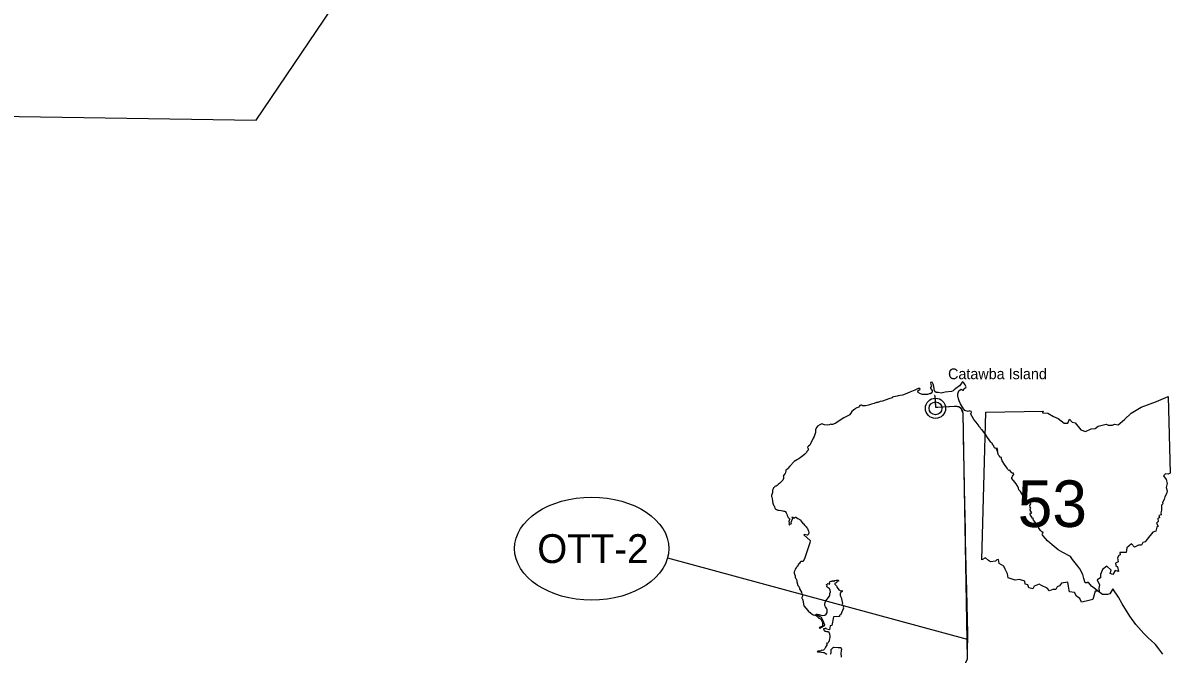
# Model space of a CAD drawing. Extents: x -82 to 873, y 0 to 440.
# Drawn here: x 400.6 to 512.1, y 215.6 to 276.9 of the extents above; entities that cross this region are included whole.
import ezdxf

# ---------------------------------------------------------------- set-up
doc = ezdxf.new("R2010")
doc.units = 0
for name, color, linetype in [('DV_X_Corp_Line', 7, 'Continuous'), ('DV_X_County_Line', 7, 'Continuous'), ('GM_P_US_Alignment', 7, 'Continuous'), ('GM_X_County', 7, 'Continuous'), ('GM_X_Interstate_Route', 7, 'Continuous'), ('PV_P_Text', 7, 'Continuous'), ('SH_Data', 7, 'Continuous')]:
    doc.layers.add(name, color=color, linetype=linetype)

msp = doc.modelspace()

# ---------------------------------------------------------------- linework, layer by layer
at = {"layer": 'DV_X_Corp_Line'}
for radius in [0.982, 0.623]:
    msp.add_circle((489.31, 239.51), radius, dxfattribs=at)
at = {"layer": 'DV_X_County_Line'}
for p, q in [((423.26, 267.51), (499.56, 380.26)), ((350.92, 268.65), (423.26, 267.51))]:
    msp.add_line(p, q, dxfattribs=at)
at = {"layer": 'GM_P_US_Alignment'}
msp.add_lwpolyline([(473.37, 168.87), (473.54, 173.99), (473.96, 183.62), (473.91, 187.53), (484.23, 206.18), (490.74, 211.48), (492.43, 215.18), (491.99, 239.02), (491.81, 239.48), (491.57, 239.64), (491.32, 239.67), (489.33, 239.58), (489.28, 240.63)], dxfattribs=at)
at = {"layer": 'GM_X_County'}
for points in [[(511.42, 215.64), (511.03, 216.15), (510.69, 216.58), (510.27, 216.95), (509.98, 217.21), (509.57, 217.62), (508.8, 218.51), (508.21, 219.33), (507.47, 220.53), (507.11, 221.17), (506.56, 221.96), (506.26, 221.5), (506.03, 221.42), (505.55, 221.43), (505.42, 221.51), (504.48, 222.22), (504.22, 222.56), (504.15, 222.62), (504.06, 222.57), (503.86, 222.56), (503.73, 222.99), (503.62, 223.37), (503.33, 223.91), (503.14, 224.16), (502.62, 224.82), (502.44, 225.13), (501.68, 225.5), (501.23, 225.76), (500.65, 226.25), (500.21, 226.63), (499.76, 227.11), (499.7, 227.21), (499.68, 227.29), (499.71, 227.35), (499.75, 227.37), (499.77, 227.48), (499.72, 227.48), (499.65, 227.52), (499.53, 227.63), (499.11, 228.3), (498.99, 228.45), (498.84, 228.64), (498.81, 228.73), (498.82, 228.8), (498.75, 228.84), (498.55, 229.12), (498.52, 229.22), (498.52, 229.29), (498.54, 229.35), (498.59, 229.37), (498.62, 229.33), (498.66, 229.35), (498.62, 229.44), (498.52, 229.61), (498.52, 229.75), (498.56, 229.75), (498.58, 229.82), (498.5, 229.92), (498.47, 230.1), (498.54, 230.17), (498.58, 230.27), (498.49, 230.39), (498.2, 230.6), (497.99, 230.8), (497.78, 231.1), (497.56, 231.44), (497.41, 231.6), (497.39, 231.75), (497.31, 231.92), (497.15, 232.17), (497.02, 232.32), (496.74, 232.7), (496.72, 232.81), (496.76, 232.84), (496.84, 232.87), (496.8, 232.95), (496.84, 233.03), (496.91, 233.06), (496.9, 233.21), (496.85, 233.22), (496.75, 233.2), (496.65, 233.3), (496.54, 233.49), (496.47, 233.46), (496.41, 233.49), (496.33, 233.56), (496.28, 233.7), (496.2, 233.8), (496.07, 233.96), (495.79, 234.42), (495.72, 234.59), (495.71, 234.73), (495.61, 234.77), (495.52, 234.85), (495.46, 234.94), (495.39, 235.05), (495.37, 235.15), (495.36, 235.31), (495.32, 235.32), (495.3, 235.36), (495.31, 235.43), (495.37, 235.44), (495.37, 235.48), (495.28, 235.48), (495.22, 235.53), (495.29, 235.55), (495.32, 235.61), (495.16, 235.6), (495.15, 235.67), (495.1, 235.64), (495.03, 235.68), (494.97, 235.81), (494.98, 235.86), (494.89, 235.92), (494.85, 236.01), (494.84, 236.1), (494.79, 236.12), (494.68, 236.23), (494.35, 236.68), (494.21, 236.94), (493.86, 237.41), (493.78, 237.45), (493.72, 237.52), (493.66, 237.66), (493.58, 237.68), (493.45, 237.91), (493.27, 238.16), (493.05, 238.43), (492.7, 239.01), (492.77, 239.02), (492.81, 239.13), (492.76, 239.21), (492.62, 239.26), (492.57, 239.22), (492.54, 239.23), (492.49, 239.21), (492.15, 239.31), (492.02, 239.47), (491.75, 239.93), (491.6, 240.25), (491.54, 240.43), (491.48, 240.73), (491.49, 240.93), (491.59, 241.2), (491.7, 241.31), (491.8, 241.38), (491.88, 241.35), (491.98, 241.28), (492.03, 241.27), (492.11, 241.42), (492.25, 241.54), (492.3, 241.6), (492.18, 241.8), (492.07, 241.99), (491.97, 242.08), (491.89, 242.04), (491.78, 241.86), (491.64, 241.71), (491.29, 241.45), (491.13, 241.31), (491.01, 241.22), (490.87, 241.15), (490.26, 241.07), (489.86, 240.99), (489.56, 241.04), (489.37, 241.06), (489.23, 241.13), (489.2, 241.21), (489.16, 241.63), (489.07, 241.86), (489, 242.04), (488.81, 242.01), (488.85, 241.81), (488.92, 241.58), (488.8, 241.54), (488.86, 241.41), (488.99, 241.23), (488.99, 241.09), (488.94, 241.01), (488.81, 240.93), (488.8, 240.95), (488.53, 240.86), (488.25, 240.84), (488.06, 240.86), (487.86, 240.92), (487.63, 241.06), (487.58, 241.21), (487.81, 241.38), (487.78, 241.44), (487.62, 241.43), (487.31, 241.26), (487.13, 241.22), (486.82, 241.08), (486.36, 240.88), (486.09, 240.78), (485.87, 240.77), (485.69, 240.72), (485.57, 240.69), (485.41, 240.65), (485.23, 240.63), (485.12, 240.58), (485.08, 240.54), (484.76, 240.43), (484.17, 240.21), (483.94, 240.17), (483.7, 240.06), (483.58, 240.09), (483.36, 239.99), (483.09, 239.9), (482.79, 239.81), (482.49, 239.75), (482.31, 239.75), (482.21, 239.76), (482.15, 239.8), (482.04, 239.82), (481.99, 239.79), (481.96, 239.78), (481.92, 239.75), (481.91, 239.7), (481.9, 239.67), (481.84, 239.63), (481.66, 239.55), (481.52, 239.49), (481.46, 239.44), (481.33, 239.34), (481.18, 239.19), (481.07, 239.04), (480.94, 238.88), (480.93, 238.86), (480.58, 238.68), (480.38, 238.58), (479.56, 238.04), (479.29, 237.94), (479.21, 237.94), (479.14, 237.96), (478.98, 237.9), (478.76, 237.86), (478.5, 237.9), (478.25, 237.99), (478.06, 237.91), (477.84, 237.76), (477.76, 237.69), (477.64, 237.44), (477.63, 237.17), (477.5, 236.77), (477.42, 236.61), (477.15, 236.05), (477.09, 235.93), (476.97, 235.82), (476.86, 235.74), (476.88, 235.62), (476.93, 235.6), (476.92, 235.46), (476.81, 235.33), (476.76, 235.22), (476.59, 235.04), (476.25, 234.75), (476.19, 234.73), (476.03, 234.6), (475.88, 234.55), (475.57, 234.33), (475.14, 233.89), (474.91, 233.64), (474.87, 233.56), (474.77, 233.49), (474.77, 233.36), (474.74, 233.3), (474.68, 233.19), (474.66, 233.13), (474.52, 232.99), (474.49, 232.93), (474.53, 232.87), (474.52, 232.7), (474.46, 232.52), (474.36, 232.42), (474.17, 232.24), (474.02, 232.1), (473.93, 232.02), (473.82, 231.95), (473.75, 231.94), (473.68, 231.9), (473.66, 231.86), (473.62, 231.82), (473.56, 231.78), (473.52, 231.69), (473.48, 231.62), (473.45, 231.53), (473.47, 231.4), (473.46, 231.31), (473.44, 231.24), (473.39, 231.15), (473.36, 231.05), (473.36, 230.94), (473.38, 230.88), (473.44, 230.76), (473.44, 230.67), (473.47, 230.55), (473.46, 230.45), (473.49, 230.28), (473.54, 230.19), (473.56, 230.11), (473.61, 230.04), (473.64, 229.94), (473.7, 229.82), (473.75, 229.76), (473.85, 229.69), (473.97, 229.62), (474.02, 229.6), (474.12, 229.6), (474.29, 229.59), (474.46, 229.56), (474.57, 229.53), (474.63, 229.51), (474.71, 229.49), (474.74, 229.44), (474.8, 229.35), (474.84, 229.23), (474.89, 229.1), (474.98, 228.9), (475.03, 228.86), (475.07, 228.82), (475.11, 228.81), (475.1, 228.71), (475.05, 228.51), (475.07, 228.39), (475.06, 228.29), (475.1, 228.2), (475.15, 228.2), (475.14, 228.26), (475.31, 228.33), (475.26, 228.45), (475.43, 228.85), (475.35, 228.89), (475.38, 228.95), (475.45, 228.92), (475.49, 228.87), (475.62, 228.88), (475.66, 228.89), (475.66, 228.92), (475.76, 228.95), (475.77, 228.91), (475.84, 228.86), (475.93, 228.81), (475.99, 228.76), (476.04, 228.75), (476.1, 228.72), (476.14, 228.68), (476.25, 228.56), (476.42, 228.31), (476.48, 228.28), (476.61, 228.14), (476.73, 228.01), (476.8, 227.91), (476.85, 227.82), (476.96, 227.59), (476.98, 227.43), (476.96, 227.27), (476.9, 227.21), (476.86, 227.2), (476.84, 227.18), (476.54, 227.26), (476.5, 227.22), (477.11, 226.66), (477.12, 226.62), (477.08, 226.44), (476.88, 225.85), (476.62, 224.97), (476.44, 224.63), (476.31, 224.64), (476.23, 224.63), (476.14, 224.55), (476.06, 224.4), (475.97, 224.33), (475.92, 224.19), (475.87, 224.16), (475.83, 224.08), (475.73, 223.99), (475.76, 223.94), (475.7, 223.9), (475.65, 223.88), (475.62, 223.77), (475.58, 223.61), (475.57, 223.48), (475.6, 223.41), (475.66, 223.24), (475.65, 223.17), (475.65, 223.11), (475.69, 223.02), (475.75, 222.95), (475.79, 222.84), (475.82, 222.78), (475.83, 222.65), (475.93, 222.3), (475.98, 222.24), (476.02, 222.21), (476.03, 222.17), (476.05, 222.15), (476.07, 222.06), (476.1, 221.98), (476.28, 221.66), (476.32, 221.44), (476.37, 221.39), (476.37, 221.26), (476.33, 221.19), (476.3, 221.13), (476.3, 221.07), (476.34, 221.03), (476.38, 220.96), (476.41, 220.88), (476.51, 220.31), (476.89, 219.86), (476.96, 219.77), (477.03, 219.71), (477.09, 219.69), (477.16, 219.62), (477.21, 219.57), (477.23, 219.55), (477.26, 219.53), (477.29, 219.53), (477.3, 219.53), (477.32, 219.51), (477.35, 219.49), (477.42, 219.46), (477.49, 219.45), (477.58, 219.42), (477.74, 219.34), (477.83, 219.29), (477.88, 219.23), (477.97, 219.13), (478.02, 219.11), (478.09, 219.06), (478.14, 219.06), (478.16, 219.04), (478.2, 219), (478.24, 218.9), (478.28, 218.8), (478.31, 218.69), (478.32, 218.47), (478.32, 218.36), (478.02, 218.22), (478.01, 218.17), (478.06, 218.15), (478.55, 218.43), (478.38, 218.87), (478.26, 219.12), (478.21, 219.18), (477.7, 219.45), (477.7, 219.51), (477.79, 219.5), (477.93, 219.47), (477.97, 219.47), (478.03, 219.44), (478.08, 219.44), (478.15, 219.4), (478.32, 219.38), (478.56, 219.43), (478.68, 219.52), (478.76, 219.66), (478.79, 219.81), (478.79, 219.96), (478.75, 220.03), (478.6, 220.21), (478.55, 220.36), (478.56, 220.49), (478.59, 220.66), (478.65, 220.82), (478.91, 221.12), (479.04, 221.32), (479.05, 221.52), (479.09, 221.67), (479.06, 221.84), (478.99, 221.99), (478.88, 222.08), (478.76, 222.15), (478.74, 222.24), (478.76, 222.3), (478.72, 222.35), (478.72, 222.39), (478.76, 222.42), (478.81, 222.47), (478.87, 222.48), (478.93, 222.46), (478.99, 222.44), (479.02, 222.5), (478.98, 222.55), (478.99, 222.58), (479.02, 222.62), (479.01, 222.64), (479.17, 222.73), (479.2, 222.73), (479.26, 222.71), (479.31, 222.75), (479.4, 222.74), (479.45, 222.67), (479.49, 222.73), (479.49, 222.78), (479.66, 222.83), (479.75, 222.82), (479.77, 222.81), (479.82, 222.8), (479.85, 222.8), (479.92, 222.75), (479.83, 222.72), (479.74, 222.71), (479.71, 222.66), (479.72, 222.61), (479.64, 222.55), (479.54, 222.53), (479.52, 222.49), (479.53, 222.43), (479.67, 222.26), (479.7, 222.21), (479.73, 222.13), (479.84, 221.97), (479.92, 221.87), (480.03, 221.81), (480.12, 221.79), (480.23, 221.8), (480.24, 221.73), (480.23, 221.7), (480.11, 221.62), (480.05, 221.55), (480.04, 221.48), (480.04, 221.31), (480.09, 221.21), (480.14, 221.12), (480.25, 220.56), (480.24, 220.48), (480.27, 220.41), (480.36, 220.32), (480.36, 220.25), (480.34, 220.18), (480.35, 220.11), (480.07, 219.4), (479.95, 219.39), (479.96, 219.28), (479.39, 219.26), (479.24, 218.42), (479.08, 218.38), (479.01, 217.99), (478.72, 218.04), (478.69, 218.11), (478.62, 218.14), (478.59, 218.11), (478.49, 218.1), (478.42, 218.08), (478.41, 218.03), (478.52, 217.97), (478.54, 217.89), (478.52, 217.85), (478.54, 217.83), (478.58, 217.85), (478.72, 217.84), (478.89, 217.84), (478.92, 217.83), (478.95, 217.77), (479.01, 217.6), (479.02, 217.36), (479.02, 217.23), (478.98, 217), (478.95, 216.82), (478.89, 216.82), (478.84, 216.69), (478.8, 216.67), (478.73, 216.68), (478.71, 216.64), (478.75, 216.61), (478.77, 216.58), (478.76, 216.55), (478.72, 216.48), (478.62, 216.29), (478.53, 216.12), (478.43, 216.03), (478.33, 215.99), (478.27, 216), (478.2, 215.98), (478.15, 215.94), (478.05, 215.91), (477.9, 215.93), (477.81, 215.9), (477.81, 215.87), (477.84, 215.84), (478.21, 215.81), (478.42, 215.8), (478.49, 215.79), (478.59, 215.72), (478.74, 215.63)], [(479.09, 215.61), (479.13, 215.69), (479.16, 215.8), (479.17, 216.04), (479.18, 216.07), (479.21, 216.11), (479.36, 216.28), (479.38, 216.29), (479.4, 216.3), (479.85, 216.28), (480.09, 216.26), (480.11, 216.25), (480.13, 216.21), (480.17, 216.1), (480.17, 216.04), (480.15, 216.01), (480.13, 215.98), (480.13, 215.9), (480.12, 215.76), (480.14, 215.33)]]:
    msp.add_lwpolyline(points, dxfattribs=at)
at = {"layer": 'GM_X_Interstate_Route'}
for points in [[(492.03, 237.27), (492.03, 237.49), (492.02, 237.7), (492, 238.53), (491.99, 238.86), (491.99, 239.02), (491.98, 239.1), (491.96, 239.18), (491.94, 239.26), (491.92, 239.3), (491.9, 239.34), (491.88, 239.38), (491.86, 239.41), (491.84, 239.45), (491.81, 239.48), (491.78, 239.5), (491.75, 239.53), (491.72, 239.56), (491.68, 239.58), (491.65, 239.6), (491.61, 239.62), (491.57, 239.64), (491.53, 239.65), (491.49, 239.66), (491.41, 239.67), (491.32, 239.67), (491.12, 239.67), (489.52, 239.59), (489.33, 239.58), (489.3, 240.34), (489.3, 240.44), (489.29, 240.54), (489.28, 240.63), (489.27, 240.67), (489.26, 240.68), (489.26, 240.7), (489.25, 240.72), (489.24, 240.73), (489.23, 240.74), (489.22, 240.75)], [(492.44, 218.22), (492.43, 218.45), (492.43, 218.49), (492.42, 219.23), (492.41, 219.43), (492.41, 219.61), (492.4, 219.88), (492.4, 219.93), (492.39, 220.31), (492.39, 220.68), (492.38, 220.91), (492.37, 221.32), (492.36, 221.85), (492.36, 221.93), (492.33, 222.84), (492.33, 222.89), (492.3, 223.83), (492.28, 224.27), (492.26, 225.21), (492.25, 225.71), (492.24, 226.4), (492.22, 227.43), (492.22, 227.59), (492.21, 228), (492.19, 228.67), (492.18, 229.27), (492.16, 230.01), (492.15, 230.62), (492.14, 231.41), (492.13, 232.05), (492.1, 233.49), (492.07, 235.25), (492.07, 235.3), (492.06, 235.42), (492.04, 236.48), (492.04, 236.73), (492.04, 236.94), (492.03, 237.27)], [(486, 207.95), (490.74, 211.48), (492.43, 215.18), (492.44, 218.22)]]:
    msp.add_lwpolyline(points, dxfattribs=at)
at = {"layer": 'PV_P_Text'}
msp.add_line((493.81, 224.78), (494.21, 239.14), dxfattribs=at)
msp.add_line((493.81, 224.78), (494.21, 239.14), dxfattribs=at)
for points in [[(494.21, 239.14), (499.78, 239.24), (499.7, 239.06), (500.22, 239.03), (500.78, 238.72), (501.25, 238.53), (501.83, 238.07), (502.18, 238.08), (502.32, 238.45), (502.59, 238.16), (502.9, 238.11), (503.45, 237.42), (503.89, 237.27), (504.43, 237.51), (504.83, 237.55), (505.13, 237.78), (505.89, 237.98), (506.1, 237.86), (506.51, 237.88), (506.71, 237.97), (507.07, 237.89), (507.69, 238.42), (508.33, 239.03), (509.31, 239.61), (510.78, 240.16), (511.94, 240.66), (512.11, 233.2)], [(494.21, 239.14), (499.78, 239.24), (499.7, 239.06), (500.22, 239.03), (500.78, 238.72), (501.25, 238.53), (501.83, 238.07), (502.18, 238.08), (502.32, 238.45), (502.59, 238.16), (502.9, 238.11), (503.45, 237.42), (503.89, 237.27), (504.43, 237.51), (504.83, 237.55), (505.13, 237.78), (505.89, 237.98), (506.1, 237.86), (506.51, 237.88), (506.71, 237.97), (507.07, 237.89), (507.69, 238.42), (508.33, 239.03), (509.31, 239.61), (510.78, 240.16), (511.94, 240.66), (512.11, 233.2)], [(512.11, 233.2), (511.94, 233.1), (511.67, 233.15), (511.49, 232.94), (511.72, 232.59), (511.82, 232.22), (511.73, 231.81), (511.82, 231.48), (511.76, 231.2), (511.59, 230.92), (511.53, 230.65), (511.39, 230.37), (511.4, 230.22), (511.27, 230.09), (511.29, 229.63), (511.22, 229.37), (511.25, 229.15), (511.02, 229.09), (511.08, 228.9), (510.93, 228.76), (510.96, 228.52), (510.81, 228.36), (510.96, 228.05), (510.84, 227.95), (510.73, 227.57), (510.45, 227.49), (509.88, 226.79), (509.68, 226.53), (509.46, 226.47), (509.34, 226.2), (509.06, 226.2), (508.64, 226.01), (508.37, 226.33), (507.9, 225.94), (507.84, 225.49), (507.24, 225.51), (507.26, 225.28), (507.13, 225.22), (507.01, 224.99), (507.08, 224.59), (506.8, 224.48), (506.83, 224.25), (507.01, 224.11), (507.09, 223.66), (506.79, 223.75), (506.55, 223.37), (506.3, 223.46), (506.38, 223.78), (505.96, 224.16), (505.56, 223.86), (505.35, 223.37), (505.34, 223.04), (505.04, 222.84), (505.24, 222.37), (505.2, 222.05), (505.21, 221.74), (504.83, 221.75), (504.61, 220.93)], [(512.11, 233.2), (511.94, 233.1), (511.67, 233.15), (511.49, 232.94), (511.72, 232.59), (511.82, 232.22), (511.73, 231.81), (511.82, 231.48), (511.76, 231.2), (511.59, 230.92), (511.53, 230.65), (511.39, 230.37), (511.4, 230.22), (511.27, 230.09), (511.29, 229.63), (511.22, 229.37), (511.25, 229.15), (511.02, 229.09), (511.08, 228.9), (510.93, 228.76), (510.96, 228.52), (510.81, 228.36), (510.96, 228.05), (510.84, 227.95), (510.73, 227.57), (510.45, 227.49), (509.88, 226.79), (509.68, 226.53), (509.46, 226.47), (509.34, 226.2), (509.06, 226.2), (508.64, 226.01), (508.37, 226.33), (507.9, 225.94), (507.84, 225.49), (507.24, 225.51), (507.26, 225.28), (507.13, 225.22), (507.01, 224.99), (507.08, 224.59), (506.8, 224.48), (506.83, 224.25), (507.01, 224.11), (507.09, 223.66), (506.79, 223.75), (506.55, 223.37), (506.3, 223.46), (506.38, 223.78), (505.96, 224.16), (505.56, 223.86), (505.35, 223.37), (505.34, 223.04), (505.04, 222.84), (505.24, 222.37), (505.2, 222.05), (505.21, 221.74), (504.83, 221.75), (504.61, 220.93)], [(504.61, 220.93), (503.96, 220.77), (503.5, 220.67), (503.35, 221.05), (503.02, 221.25), (502.81, 221.62), (502.35, 221.68), (502.24, 222.19), (502.19, 222.61), (501.55, 222.51), (501.38, 222.25), (501.15, 222.18), (501.02, 221.92), (500.72, 221.9), (500.39, 221.78), (500.17, 222.03), (499.63, 222.29), (499.39, 222.42), (498.89, 222.22), (498.78, 221.98), (498.37, 222.08), (498.28, 222.35), (498.04, 222.43), (497.98, 222.72), (497.46, 222.87), (497.06, 222.81), (496.36, 223.04), (496.32, 223.42), (496.08, 223.88), (495.95, 224.19), (495.51, 224.44), (495.42, 224.82), (495.27, 224.8), (495.14, 224.65), (494.65, 224.58), (494.45, 224.73), (494.18, 225), (493.81, 224.78)], [(504.61, 220.93), (503.96, 220.77), (503.5, 220.67), (503.35, 221.05), (503.02, 221.25), (502.81, 221.62), (502.35, 221.68), (502.24, 222.19), (502.19, 222.61), (501.55, 222.51), (501.38, 222.25), (501.15, 222.18), (501.02, 221.92), (500.72, 221.9), (500.39, 221.78), (500.17, 222.03), (499.63, 222.29), (499.39, 222.42), (498.89, 222.22), (498.78, 221.98), (498.37, 222.08), (498.28, 222.35), (498.04, 222.43), (497.98, 222.72), (497.46, 222.87), (497.06, 222.81), (496.36, 223.04), (496.32, 223.42), (496.08, 223.88), (495.95, 224.19), (495.51, 224.44), (495.42, 224.82), (495.27, 224.8), (495.14, 224.65), (494.65, 224.58), (494.45, 224.73), (494.18, 225), (493.81, 224.78)]]:
    msp.add_lwpolyline(points, dxfattribs=at)
at = {"layer": 'SH_Data'}
msp.add_line((463.26, 224.99), (492.4, 217.08), dxfattribs=at)
msp.add_ellipse((455.88, 225.88), major_axis=(7.5, 0), ratio=0.666667, dxfattribs=at)

# ---------------------------------------------------------------- texts
at = {"layer": 'DV_X_Corp_Line'}
msp.add_text('Catawba Island', height=1.0417, rotation=0.005, dxfattribs=at).set_placement((490.53, 242.34))
at = {"layer": 'PV_P_Text'}
msp.add_text('53', height=4.528, rotation=0.005, dxfattribs=at).set_placement((497.3, 227.98))
at = {"layer": 'SH_Data'}
msp.add_text('OTT-2', height=2.8, dxfattribs=at).set_placement((450.59, 224.48))

doc.saveas('drawing.dxf')
